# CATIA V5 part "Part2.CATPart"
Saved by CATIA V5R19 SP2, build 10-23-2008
Part number: Part2
Bounding box of the stored display mesh (mm): x -7.5 to 7.5, y -7.302 to 7.5, z -7.5 to 7.5
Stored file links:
  C:\Documents and Settings\jurc\Plocha\Nový priečinok\Part2.CATPart
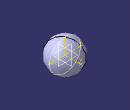
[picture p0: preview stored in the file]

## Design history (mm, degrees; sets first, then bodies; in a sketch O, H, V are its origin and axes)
Body1 (main body)
  Sketch1 on yz-plane, origin (0, 0, 0), H (0, 1, 0), V (0, 0, 1)
    arc A1 centre (0, 0) radius 7.5 from (0, -7.5) to (0, 7.5) ccw
    line L1 (0, 7.5) -> (0, -7.5)
    radius A1 = 7.5
    vertical: L1 V
  Shaft1: profile Sketch1, axis Sketch1.V, angle 360
  Sketch2 on zx-plane, origin (0, 0, 0), H (-1, 0, 0), V (0, 0, 1)
    circle A1 centre (0, 0) radius 7.5
    point P1 (0, 0)
    radius A1 = 7.5
    coincidence: P1 O
  Sketch3 on xy-plane, origin (0, 0, 0), H (1, 0, 0), V (0, 1, 0)
    point P1 (0, 7.5)
    coincidence: P1 V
